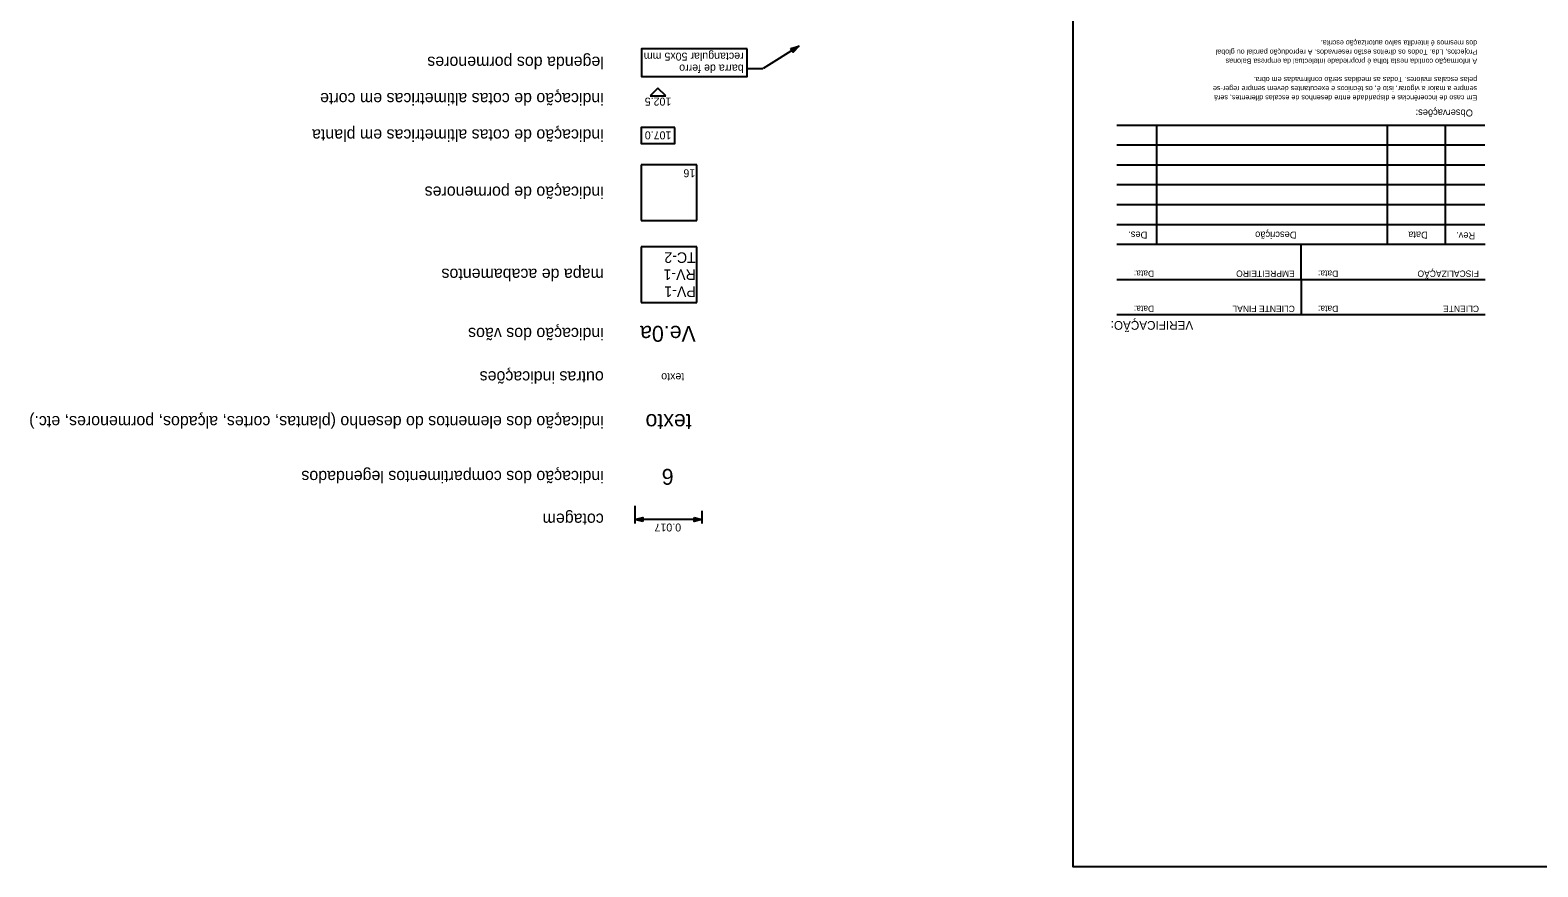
# Model space of a CAD drawing. Extents: x 1306.3 to 1323.2, y -308.3 to -299.9.
# Drawn here: x 1306.33 to 1313.92, y -308.35 to -304.14 of the extents above; entities that cross this region are included whole.
import ezdxf

# ---------------------------------------------------------------- set-up
doc = ezdxf.new("R2010")
doc.units = 0
for name, color, linetype in [('Level 57', 7, 'Continuous'), ('Level 58', 7, 'Continuous'), ('Level 60', 7, 'Continuous'), ('Level 61', 7, 'Continuous'), ('Level 62', 7, 'Continuous')]:
    doc.layers.add(name, color=color, linetype=linetype)

msp = doc.modelspace()

# ---------------------------------------------------------------- linework, layer by layer
at = {"layer": 'Level 57'}
for p, q in [((1309.6861, -305.2262), (1309.4061, -305.2262)), ((1309.4061, -305.2262), (1309.4061, -305.5062)), ((1309.6861, -305.5062), (1309.6861, -305.2262)), ((1309.4061, -305.5062), (1309.6861, -305.5062))]:
    msp.add_line(p, q, dxfattribs=at)
at = {"layer": 'Level 58'}
for p, q in [((1309.6861, -304.8128), (1309.4061, -304.8128)), ((1309.4061, -304.8128), (1309.4061, -305.0928)), ((1309.6861, -305.0928), (1309.6861, -304.8128)), ((1309.4061, -305.0928), (1309.6861, -305.0928))]:
    msp.add_line(p, q, dxfattribs=at)
at = {"layer": 'Level 60'}
for p, q in [((1310.1977, -304.2162), (1310.0185, -304.329)), ((1309.9381, -304.3294), (1310.0181, -304.3294))]:
    msp.add_line(p, q, dxfattribs=at)
for points in [[(1310.1585, -304.229), (1310.1977, -304.2162), (1310.1693, -304.246)], [(1309.9381, -304.2296), (1309.4063, -304.2296), (1309.4063, -304.3694), (1309.9381, -304.3694)]]:
    msp.add_lwpolyline(points, close=True, dxfattribs=at)
at = {"layer": 'Level 61'}
for p, q in [((1309.4899, -304.4272), (1309.4499, -304.4672)), ((1309.5297, -304.4672), (1309.4899, -304.4272)), ((1309.4499, -304.4672), (1309.5297, -304.4672)), ((1309.3737, -306.5287), (1309.3737, -306.6181)), ((1309.7113, -306.5537), (1309.7113, -306.6181)), ((1309.7113, -306.5981), (1309.3737, -306.5981))]:
    msp.add_line(p, q, dxfattribs=at)
for points in [[(1309.5747, -304.6252), (1309.4061, -304.6252), (1309.4061, -304.7054), (1309.5745, -304.7054)], [(1309.4137, -306.6081), (1309.3737, -306.5981), (1309.4137, -306.5881)], [(1309.6713, -306.5881), (1309.7113, -306.5981), (1309.6713, -306.6081)]]:
    msp.add_lwpolyline(points, close=True, dxfattribs=at)
at = {"layer": 'Level 62'}
for p, q in [((1313.6492, -304.6148), (1311.797, -304.6148)), ((1311.997, -304.6148), (1311.997, -305.2148)), ((1313.1578, -304.6148), (1313.1578, -305.2148)), ((1313.4492, -304.6148), (1313.449, -305.2148)), ((1313.6492, -304.7148), (1311.797, -304.7148)), ((1313.649, -304.8148), (1311.7972, -304.8148)), ((1313.649, -304.9148), (1311.797, -304.9148)), ((1313.6492, -305.0148), (1311.797, -305.0148)), ((1313.6492, -305.1148), (1311.7972, -305.1148)), ((1313.6498, -305.2148), (1311.7976, -305.2148)), ((1312.7238, -305.2149), (1312.7244, -305.5689)), ((1313.6505, -305.3919), (1311.7985, -305.3919)), ((1313.6504, -305.5688), (1311.7982, -305.5688))]:
    msp.add_line(p, q, dxfattribs=at)
msp.add_lwpolyline([(1323.1772, -299.9454), (1323.1772, -308.3454), (1311.5776, -308.3454), (1311.5776, -299.9454)], close=True, dxfattribs=at)

# ---------------------------------------------------------------- texts
at = {"layer": 'Level 57'}
for s, p in [('TC-2', (1309.6801, -305.2536)), ('RV-1', (1309.6801, -305.3394)), ('PV-1', (1309.6801, -305.4252))]:
    msp.add_text(s, height=0.0532, rotation=180.00001, dxfattribs=at).set_placement(p)
at = {"layer": 'Level 58'}
msp.add_text('16', height=0.04, rotation=180.00004, dxfattribs=at).set_placement((1309.6775, -304.836))
at = {"layer": 'Level 60'}
for s, height, rotation, p in [('legenda dos pormenores', 0.06, 180.00001, (1309.2175, -304.2694)), ('rectangular 50x5 mm', 0.04, 180, (1309.9209, -304.249)), ('barra de ferro', 0.04, 180, (1309.9209, -304.309)), ('indicação de cotas altimetricas em corte', 0.06, 180.00001, (1309.2175, -304.4522)), ('indicação de cotas altimetricas em planta', 0.06, 180.00001, (1309.2175, -304.635)), ('indicação de pormenores', 0.06, 180.00001, (1309.2175, -304.9226)), ('mapa de acabamentos', 0.06, 180.00001, (1309.2175, -305.336)), ('indicação dos vãos', 0.06, 180.00001, (1309.2175, -305.6336)), ('Ve.0a', 0.08, 180.00001, (1309.6797, -305.6236)), ('outras indicações', 0.06, 180.00001, (1309.2175, -305.852)), ('texto', 0.04, 179.99997, (1309.6223, -305.862)), ('indicação dos elementos do desenho (plantas, cortes, alçados, pormenores, etc.)', 0.06, 180.00001, (1309.2175, -306.0774)), ('texto', 0.08, 180.00001, (1309.6593, -306.0676)), ('indicação dos compartimentos legendados', 0.06, 180.00001, (1309.2175, -306.3532)), ('6', 0.08, 180, (1309.5687, -306.3432)), ('cotagem', 0.06, 180.00001, (1309.2175, -306.5682))]:
    msp.add_text(s, height=height, rotation=rotation, dxfattribs=at).set_placement(p)
at = {"layer": 'Level 61'}
for s, rotation, p in [('102.5', 180.0002, (1309.5571, -304.4754)), ('107.0', 180.00017, (1309.5575, -304.6452)), ('0.017', 180, (1309.6063, -306.618))]:
    msp.add_text(s, height=0.04, rotation=rotation, dxfattribs=at).set_placement(p)
at = {"layer": 'Level 62'}
for s, height, rotation, p in [('dos mesmos é interdita salvo autorização escrita.', 0.026, 179.99999, (1313.61, -304.1876)), ('Projectos, Lda. Todos os direitos estão reservados. A reprodução parcial ou global', 0.026, 179.99999, (1313.61, -304.2336)), ('A informação contida nesta folha é propriedade intelectual da empresa Balonas', 0.026, 179.99999, (1313.61, -304.2796)), ('pelas escalas maiores. Todas as medidas serão confirmadas em obra.', 0.026, 179.99999, (1313.61, -304.3716)), ('sempre a maior a vigorar, isto é, os técnicos e executantes devem sempre reger-se', 0.026, 179.99999, (1313.61, -304.4176)), ('Em caso de incoerências e disparidade entre desenhos de escalas diferentes, será', 0.026, 179.99999, (1313.6098, -304.4636)), ('Observações:', 0.035, 179.99999, (1313.5888, -304.5352)), ('Des.', 0.035, 179.99999, (1311.951, -305.1492)), ('Descrição', 0.035, 179.99999, (1312.7014, -305.1492)), ('Data', 0.035, 179.99999, (1313.3618, -305.1492)), ('Rev.', 0.035, 179.99999, (1313.6004, -305.1532)), ('Data:', 0.03199, 179.99997, (1311.9854, -305.3452)), ('EMPREITEIRO', 0.031994, 179.99997, (1312.6926, -305.3452)), ('Data:', 0.03199, 179.99997, (1312.9114, -305.3452)), ('FISCALIZAÇÃO', 0.031994, 179.99997, (1313.619, -305.3452)), ('VERIFICAÇÃO:', 0.043997, 179.99997, (1312.182, -305.5992)), ('Data:', 0.03199, 179.99997, (1311.9854, -305.5222)), ('CLIENTE FINAL', 0.031994, 179.99997, (1312.693, -305.5222)), ('Data:', 0.03199, 179.99997, (1312.9116, -305.5222)), ('CLIENTE', 0.03199, 179.99997, (1313.6194, -305.5222))]:
    msp.add_text(s, height=height, rotation=rotation, dxfattribs=at).set_placement(p)

doc.saveas('drawing.dxf')
